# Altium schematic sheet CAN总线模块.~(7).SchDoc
size A4
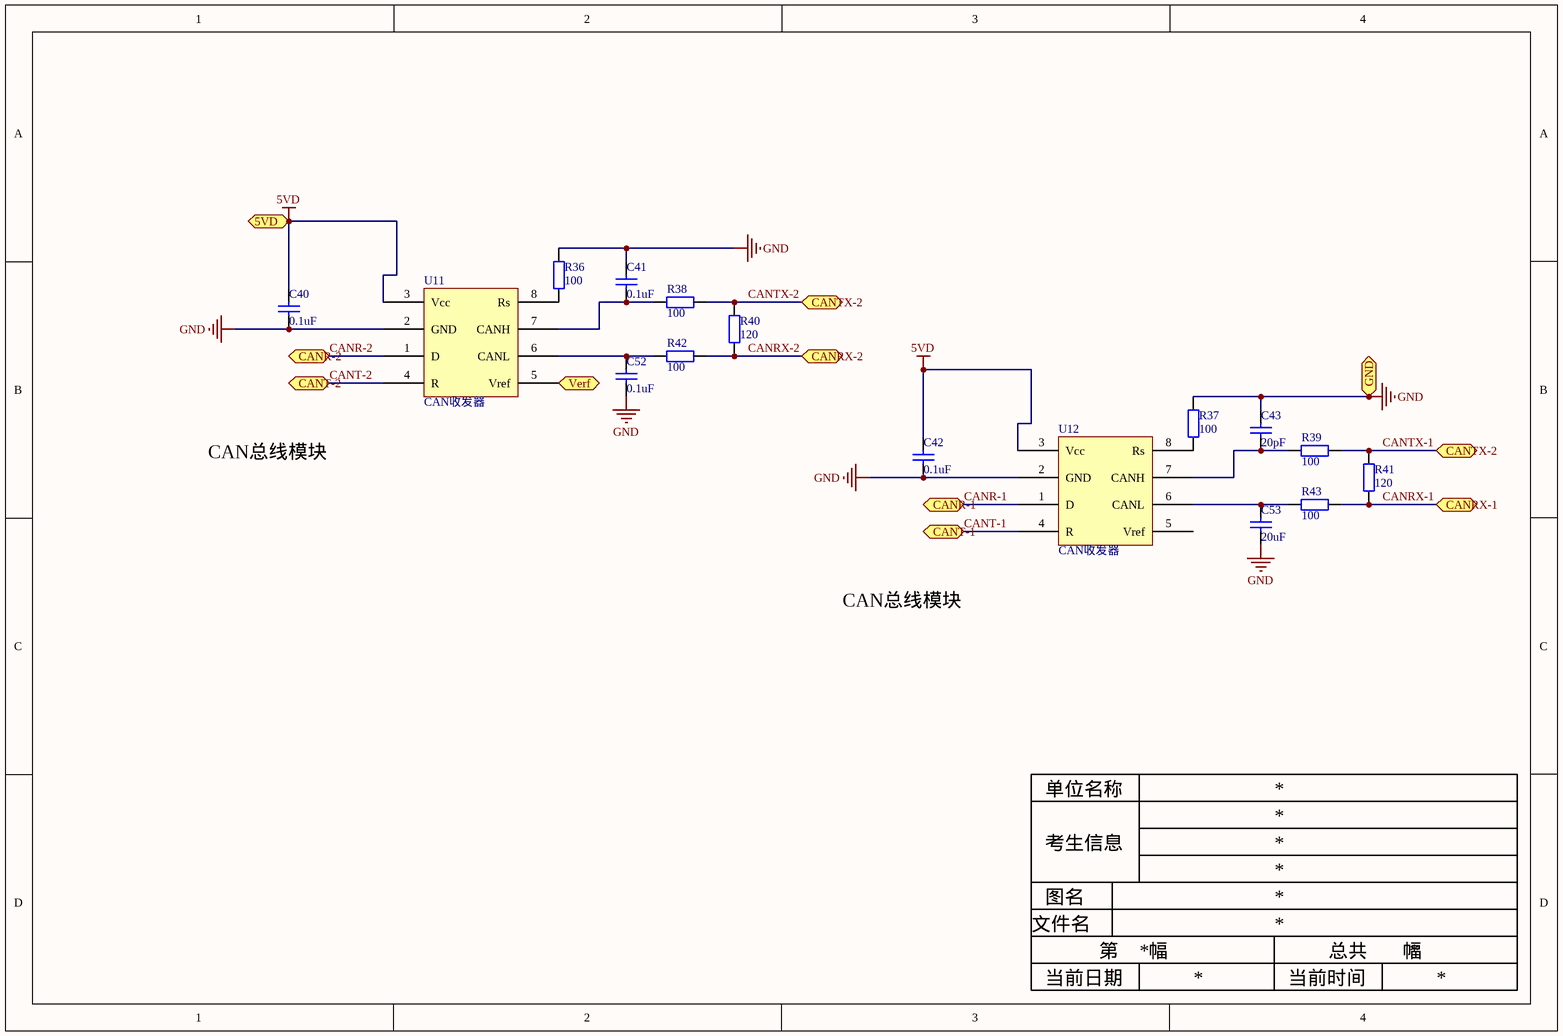
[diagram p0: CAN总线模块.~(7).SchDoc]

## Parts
C40  value 0.1uF  [RAD-0.3]  (hidden comment: Cap)
C41  value 0.1uF  [RAD-0.3]  (hidden comment: Cap)
C42  value 0.1uF  [RAD-0.3]  (hidden comment: Cap)
C43  value 20pF  [RAD-0.3]  (hidden comment: Cap)
C52  value 0.1uF  [RAD-0.3]  (hidden comment: Cap)
C53  value 20uF  [RAD-0.3]  (hidden comment: Cap)
R36  100  [R0603]
R37  100  [R0603]
R38  100  [R0603]
R39  100  [R0603]
R40  120  [R0603]
R41  120  [R0603]
R42  100  [R0603]
R43  100  [R0603]
U11  CAN收发器  [CAN]
U12  CAN收发器  [CAN]

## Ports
5VD, CANR-1, CANR-2, CANRX-1, CANRX-2, CANT-1, CANT-2, CANTX-2, GND, Verf

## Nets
5VD: C40.2 C42.2 U11.3(Vcc) U12.3(Vcc) ; port 5VD
GND: C40.1 C41.2 C42.1 C43.2 C52.1 C53.1 R36.2 R37.2 U11.2(GND) U12.2(GND) ; port GND
CANR-1: U12.1(D) ; port CANR-1
CANR-2: U11.1(D) ; port CANR-2
CANRX-1: R41.2 R43.1 ; port CANRX-1
CANRX-2: R40.2 R42.1 ; port CANRX-2
CANT-1: U12.4(R) ; port CANT-1
CANT-2: U11.4(R) ; port CANT-2
CANTX-1: R38.1 R39.1 R40.1 R41.1 ; port CANTX-2  [also labelled CANTX-2]
Verf: U11.5(Vref) ; port Verf
NetC41_1: C41.1 R38.2 U11.7(CANH)
NetC43_1: C43.1 R39.2 U12.7(CANH)
NetC52_2: C52.2 R42.2 U11.6(CANL)
NetC53_2: C53.2 R43.2 U12.6(CANL)
NetR36_1: R36.1 U11.8(Rs)
NetR37_1: R37.1 U12.8(Rs)

Not connected (* = marked no-connect by the designer): U12 5(Vref)

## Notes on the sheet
- 单位名称
- 考生信息
- 图名
- 文件名
- 当前日期
- 第      幅
- 当前时间
- 总共       幅
- Labels drawn without touching a wire or pin: CAN总线模块

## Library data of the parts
C40-C43 C52 C53 = Cap: Capacitor
R36-R43 = R0603
U11 U12 = CAN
